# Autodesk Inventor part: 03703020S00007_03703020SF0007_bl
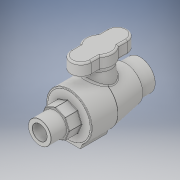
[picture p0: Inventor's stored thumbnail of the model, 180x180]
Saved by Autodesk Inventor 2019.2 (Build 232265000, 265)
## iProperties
Created: 2022-04
Part Number: 03703020S00007_03703020SF0007_bl
Material: Generic
Description: PA Ball Valve Female 3/4'' x Male 3/4''
Document SubType Name: Modeling
Designer: Lenora
Density: 1 g/cm^3
Appearance: Default
Author: Lenora
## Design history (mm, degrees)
derived "0370302.ipt"
feature "Solid1::0370302.ipt" dims "ScaleForDerivedMember" = 10
tag "TaggingFeature1"
body "Solid1"
other parameters: "d0" = 117 [user parameter], "d1" = 18 [user parameter], "d2" = 19 [user parameter], "d3" = 1.9 [user parameter], "d4" = 26.441 [user parameter], "d8" = 24.117 [user parameter], "d10" = 100 deg [user parameter], "d12" = 14.4 [user parameter], "d14" = 17.55 [user parameter], "d15" = 20.25 [user parameter], "d16" = 47.97 [user parameter], "d17" = 17 [user parameter], "d19" = 1 [user parameter], "d20" = 29.25 [user parameter], "d21" = 54 [user parameter], "d22" = 85 deg [user parameter], "d23" = 16.2 [user parameter], "d24" = 31.59 [user parameter], "d25" = 1 [user parameter], "d26" = 14.625 [user parameter], "d27" = 53 [user parameter], "d34" = 21.06 [user parameter], "d35" = 11.7 [user parameter], "d37" = 0 [user parameter], "d39" = 360 deg [user parameter], "d41" = 49.29 [user parameter], "d42" = 80 deg [user parameter], "d43" = 27 [user parameter], "d44" = 26.5 [user parameter], "d45" = 70 deg [user parameter], "d46" = 70 deg [user parameter], "d48" = 0 [user parameter], "d50" = 0 [user parameter], "d51" = 0.5 [user parameter], "d52" = 0.25 [user parameter], "d55" = 2 [user parameter], "d56" = 2 [user parameter], "d57" = 2 [user parameter], "Rc" = 24.117 [user parameter], "R" = 26.441 [user parameter], "A1" = 27 [user parameter], "A2" = 54 [user parameter], "H_" = 117 [user parameter], "l1" = 19 [user parameter], "l2" = 18 [user parameter], "E_" = 53 [user parameter]
